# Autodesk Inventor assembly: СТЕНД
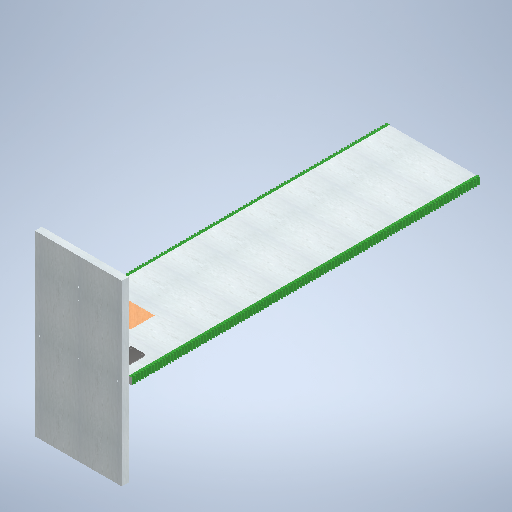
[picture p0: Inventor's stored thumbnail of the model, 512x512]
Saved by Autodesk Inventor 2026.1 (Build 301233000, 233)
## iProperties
Created: 2025-12
Part Number: СТЕНД
Document SubType Name: Assembly
Designer: Yury Melnikov
Author: Yury Melnikov
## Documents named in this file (7)
- C:\Users\user\Documents\Проекты\ВсОШ_РОБО\Стенд\СТЕНД.iam
- C:\Users\user\Documents\Проекты\ВсОШ_РОБО\Стенд\МОДЕЛИ\ЛДСП.ipt
- C:\Users\user\Documents\Проекты\ВсОШ_РОБО\Стенд\МОДЕЛИ\РЕЙКА.ipt
- C:\Users\user\Documents\Проекты\ВсОШ_РОБО\Стенд\МОДЕЛИ\РЕЙКА_MIR.ipt
- C:\Users\user\Documents\Проекты\ВсОШ_РОБО\Стенд\МОДЕЛИ\ЛДСП_НИЗ.ipt
- C:\Users\user\Documents\Проекты\ВсОШ_РОБО\Стенд\МОДЕЛИ\УГОЛОК.ipt
- C:\Users\user\Documents\Проекты\ВсОШ_РОБО\Стенд\МОДЕЛИ\РЕБРО.ipt
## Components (13 placed, 6 different names)
1. ЛДСП:1 — Совмещение:1, Заподлицо:1, Совмещение:2, Заподлицо:2, Совмещение:5, Совмещение:6, Совмещение:7, Совмещение:8, Совмещение:10, Совмещение:13, Совмещение:16, Совмещение:17, Заподлицо:3
2. РЕЙКА_MIR:1 — Совмещение:16, Совмещение:17, Заподлицо:3
3. РЕЙКА_MIR:2
4. РЕЙКА_MIR:3
5. РЕЙКА_MIR:4
6. ЛДСП_НИЗ:1 — Совмещение:5, Совмещение:6, Совмещение:7, Совмещение:9, Совмещение:11, Совмещение:12
7. УГОЛОК:1 — Совмещение:8, Совмещение:9
8. УГОЛОК:2 — Совмещение:10, Совмещение:11
9. РЕБРО:1 — Совмещение:12, Совмещение:13
10. РЕЙКА:1 — Совмещение:1, Заподлицо:1, Совмещение:2
11. РЕЙКА:2
12. РЕЙКА:3
13. РЕЙКА:4
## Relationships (16: Mate 13, Flush 3)
- Совмещение:1 [Mate]: ЛДСП:1 ↔ РЕЙКА:1
- Заподлицо:1 [Flush]: ЛДСП:1 ↔ РЕЙКА:1
- Совмещение:2 [Mate]: ЛДСП:1 ↔ РЕЙКА:1
- Заподлицо:2 [Flush]: ЛДСП:1
- Совмещение:5 [Mate]: ЛДСП:1 ↔ ЛДСП_НИЗ:1
- Совмещение:6 [Mate]: ЛДСП:1 ↔ ЛДСП_НИЗ:1
- Совмещение:7 [Mate]: ЛДСП:1 ↔ ЛДСП_НИЗ:1
- Совмещение:8 [Mate]: ЛДСП:1 ↔ УГОЛОК:1
- Совмещение:9 [Mate]: ЛДСП_НИЗ:1 ↔ УГОЛОК:1
- Совмещение:10 [Mate]: ЛДСП:1 ↔ УГОЛОК:2
- Совмещение:11 [Mate]: ЛДСП_НИЗ:1 ↔ УГОЛОК:2
- Совмещение:12 [Mate]: ЛДСП_НИЗ:1 ↔ РЕБРО:1
- Совмещение:13 [Mate]: ЛДСП:1 ↔ РЕБРО:1
- Совмещение:16 [Mate]: ЛДСП:1 ↔ РЕЙКА_MIR:1
- Совмещение:17 [Mate]: ЛДСП:1 ↔ РЕЙКА_MIR:1
- Заподлицо:3 [Flush]: ЛДСП:1 ↔ РЕЙКА_MIR:1
